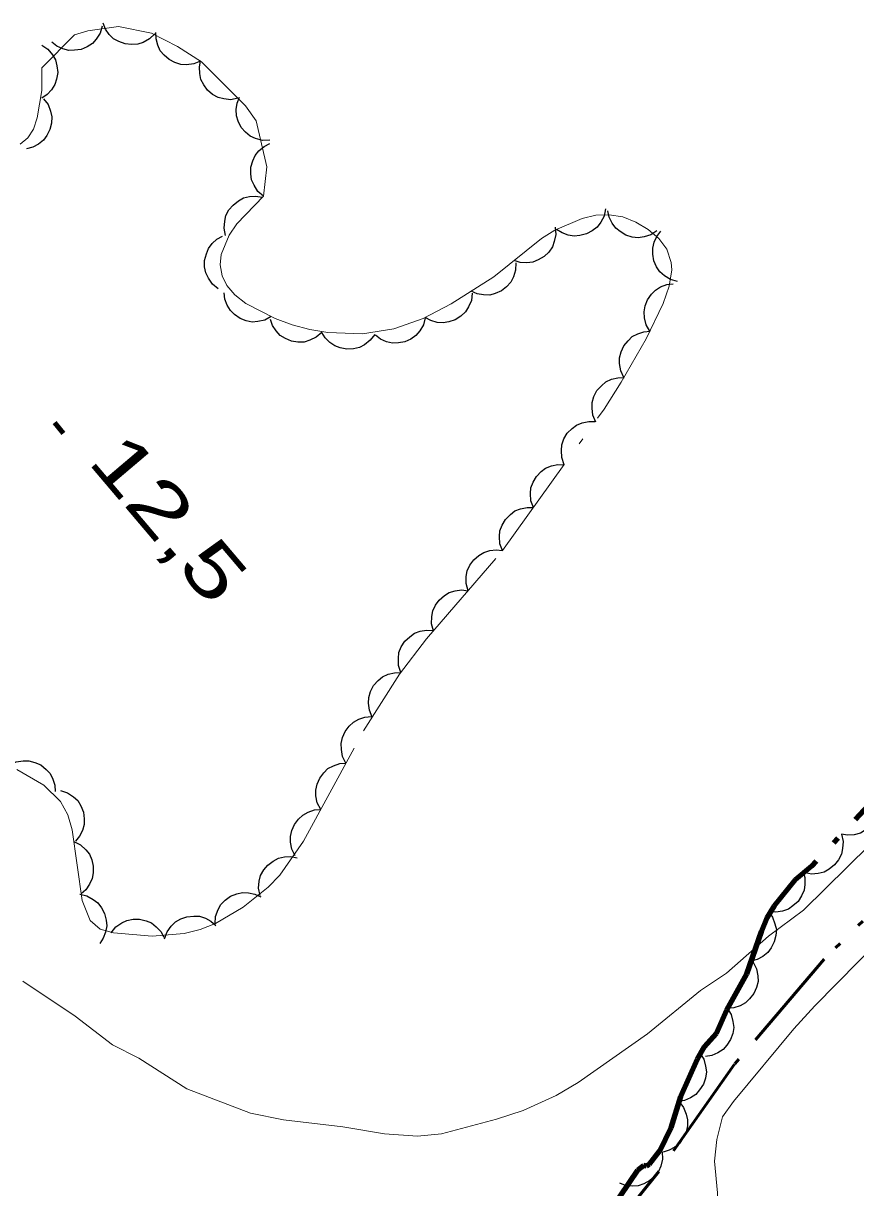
# Model space of a CAD drawing. Extents: x 386081 to 389416, y 5130568 to 5134082.
# Drawn here: x 387292.6 to 387339.8, y 5132364.4 to 5132430.4 of the extents above; entities that cross this region are included whole.
import ezdxf

# ---------------------------------------------------------------- set-up
doc = ezdxf.new("R2010")
doc.units = 0
doc.header["$LTSCALE"] = 1.2
for name, pattern in [('DASH_DOUBLE_DOT', [9.2, 5, -1.2, 0.3, -1.2, 0.3, -1.2]), ('DOT_DASHED', [7.7, 5, -1.2, 0.3, -1.2]), ('LONG_DASHED', [7.5, 6, -1.5])]:
    doc.linetypes.add(name, pattern=pattern)
for name, color, linetype, lineweight in [('2', 7, 'Continuous', 13), ('3', 7, 'Continuous', 140), ('4', 7, 'DASH_DOUBLE_DOT', 53), ('44', 7, 'Continuous', 25)]:
    doc.layers.add(name, color=color, linetype=linetype, lineweight=lineweight)

msp = doc.modelspace()

# ---------------------------------------------------------------- linework, layer by layer
at = {"layer": '2'}
for points in [[(387328.02, 5132373.16), (387331.01, 5132375.62), (387332.5, 5132376.6), (387334.87, 5132378.7), (387336.85, 5132380.17), (387340.59, 5132383.86)], [(387341.24, 5132378.55), (387337.5, 5132374.74), (387336.31, 5132373.45), (387332.88, 5132369.32), (387332.26, 5132368.46), (387331.94, 5132367.17), (387331.81, 5132365.94), (387331.98, 5132364.15), (387331.91, 5132362.48), (387332.15, 5132361.12), (387332.45, 5132360.07), (387332.81, 5132359.21), (387333.55, 5132358.34), (387334.17, 5132358.09), (387336.02, 5132357.84), (387337.2, 5132357.9), (387339.24, 5132358.32), (387341.03, 5132358.5)]]:
    msp.add_lwpolyline(points, dxfattribs=at)
at = {"layer": '2', "linetype": 'LONG_DASHED'}
msp.add_lwpolyline([(387292.61, 5132376.15), (387295.58, 5132374.16), (387297.69, 5132372.54), (387299.18, 5132371.79), (387301.91, 5132370.04), (387305.51, 5132368.66), (387307.38, 5132368.28), (387310.74, 5132367.89), (387313.1, 5132367.5), (387314.97, 5132367.37), (387316.34, 5132367.49), (387319.46, 5132368.33), (387320.96, 5132368.82), (387322.83, 5132369.67), (387324.08, 5132370.41), (387328.02, 5132373.16)], dxfattribs=at)
at = {"layer": '3'}
msp.add_line((387294.39, 5132407.81), (387294.9, 5132407.2), dxfattribs=at)
at = {"layer": '4'}
msp.add_lwpolyline([(387385.14, 5132422.65), (387378, 5132415.91), (387345.53, 5132384.75), (387338.02, 5132377.4), (387332.95, 5132371.44), (387328.66, 5132365.36), (387323.45, 5132358.88), (387320.1, 5132355.51), (387317.98, 5132352.68), (387317.57, 5132352.26), (387316.14, 5132350.32), (387313.69, 5132346.48), (387308.47, 5132338.84), (387304.07, 5132332.7)], dxfattribs=at)
at = {"layer": '44', "linetype": 'DOT_DASHED', "lineweight": 13}
for points in [[(387306.24, 5132420.64), (387306.44, 5132422.31), (387305.83, 5132424.91), (387305.22, 5132425.77), (387302.74, 5132428.26), (387301.38, 5132429.13), (387299.89, 5132429.88), (387298.02, 5132430.26), (387296.28, 5132430.02), (387295.53, 5132429.78), (387293.68, 5132427.92), (387293.68, 5132426.63), (387293.42, 5132425.09), (387293.2, 5132424.44), (387292.88, 5132423.94), (387292.45, 5132423.59)], [(387325.85, 5132419.59), (387325.09, 5132419.57), (387324.31, 5132419.37), (387322.76, 5132418.72), (387322, 5132418.25), (387319.31, 5132416.07), (387316.89, 5132414.53), (387315.29, 5132413.7), (387313.63, 5132413.12), (387311.85, 5132412.83), (387309.89, 5132412.91), (387308.88, 5132413.09), (387307.88, 5132413.34), (387306.91, 5132413.71), (387305.24, 5132414.55), (387304.62, 5132415.04), (387304.17, 5132415.57), (387303.9, 5132416.13), (387303.79, 5132416.75), (387303.84, 5132417.34), (387304.3, 5132418.44), (387304.73, 5132419.07), (387306.24, 5132420.64)], [(387292.26, 5132388.15), (387293.8, 5132387.26), (387294.74, 5132386.34), (387295.15, 5132385.57), (387295.4, 5132384.72), (387295.97, 5132380.71), (387296.43, 5132379.58), (387296.98, 5132379.09), (387297.74, 5132378.88), (387299.94, 5132378.7), (387301.75, 5132378.84), (387302.65, 5132379.07), (387303.52, 5132379.41), (387305.09, 5132380.34), (387306.52, 5132381.48), (387307.18, 5132382.15), (387308.51, 5132384.09), (387311.92, 5132390.34), (387313.96, 5132393.54), (387315.49, 5132395.55), (387319.8, 5132400.55), (387325.55, 5132408.57), (387326.52, 5132410.09), (387327.93, 5132412.55), (387328.91, 5132414.55), (387329.25, 5132415.54), (387329.39, 5132416.46), (387329.36, 5132416.88), (387329.11, 5132417.63), (387328.66, 5132418.25), (387328.05, 5132418.76), (387327.35, 5132419.17), (387326.61, 5132419.47), (387325.85, 5132419.59)]]:
    msp.add_lwpolyline(points, dxfattribs=at)
at = {"layer": '44'}
for points in [[(387297.11, 5132430.28), (387296.99, 5132429.88), (387296.77, 5132429.54), (387296.55, 5132429.29), (387296.25, 5132429.1), (387295.91, 5132428.96), (387295.53, 5132428.91), (387295.21, 5132428.9), (387294.87, 5132428.99), (387294.53, 5132429.15), (387294.25, 5132429.37)], [(387300.09, 5132429.84), (387299.79, 5132429.55), (387299.43, 5132429.36), (387299.12, 5132429.25), (387298.77, 5132429.23), (387298.4, 5132429.27), (387298.04, 5132429.41), (387297.75, 5132429.55), (387297.5, 5132429.8), (387297.29, 5132430.1), (387297.15, 5132430.44)], [(387302.67, 5132428.3), (387302.29, 5132428.14), (387301.89, 5132428.09), (387301.56, 5132428.1), (387301.22, 5132428.21), (387300.89, 5132428.38), (387300.61, 5132428.64), (387300.39, 5132428.88), (387300.25, 5132429.2), (387300.16, 5132429.56), (387300.15, 5132429.92)], [(387293.68, 5132429.2), (387294.03, 5132428.97), (387294.28, 5132428.65), (387294.45, 5132428.37), (387294.54, 5132428.03), (387294.58, 5132427.66), (387294.51, 5132427.28), (387294.42, 5132426.97), (387294.23, 5132426.67), (387293.98, 5132426.4), (387293.68, 5132426.2)], [(387304.8, 5132426.19), (387304.39, 5132426.11), (387303.99, 5132426.16), (387303.67, 5132426.23), (387303.36, 5132426.41), (387303.08, 5132426.65), (387302.86, 5132426.96), (387302.7, 5132427.25), (387302.63, 5132427.59), (387302.62, 5132427.96), (387302.68, 5132428.32)], [(387293.78, 5132426.16), (387294.04, 5132425.83), (387294.18, 5132425.45), (387294.25, 5132425.13), (387294.23, 5132424.77), (387294.14, 5132424.42), (387293.96, 5132424.08), (387293.77, 5132423.81), (387293.49, 5132423.59), (387293.17, 5132423.42), (387292.82, 5132423.32)], [(387306.61, 5132423.81), (387306.19, 5132423.8), (387305.8, 5132423.91), (387305.5, 5132424.04), (387305.23, 5132424.26), (387304.99, 5132424.54), (387304.82, 5132424.89), (387304.71, 5132425.2), (387304.7, 5132425.55), (387304.75, 5132425.92), (387304.88, 5132426.25)], [(387306.24, 5132420.64), (387305.92, 5132420.91), (387305.71, 5132421.26), (387305.57, 5132421.56), (387305.52, 5132421.91), (387305.53, 5132422.28), (387305.64, 5132422.64), (387305.77, 5132422.94), (387305.99, 5132423.21), (387306.28, 5132423.45), (387306.6, 5132423.62)], [(387304.1, 5132418.41), (387304.01, 5132418.82), (387304.05, 5132419.23), (387304.12, 5132419.55), (387304.29, 5132419.86), (387304.52, 5132420.14), (387304.83, 5132420.37), (387305.11, 5132420.54), (387305.45, 5132420.62), (387305.82, 5132420.64), (387306.18, 5132420.58)], [(387325.63, 5132419.92), (387325.55, 5132419.51), (387325.36, 5132419.16), (387325.16, 5132418.89), (387324.88, 5132418.67), (387324.56, 5132418.5), (387324.18, 5132418.41), (387323.86, 5132418.37), (387323.51, 5132418.44), (387323.17, 5132418.57), (387322.86, 5132418.76)], [(387328.55, 5132418.68), (387328.21, 5132418.45), (387327.82, 5132418.33), (387327.49, 5132418.28), (387327.14, 5132418.32), (387326.79, 5132418.43), (387326.46, 5132418.63), (387326.21, 5132418.83), (387326.01, 5132419.12), (387325.85, 5132419.46), (387325.77, 5132419.81)], [(387322.78, 5132418.88), (387322.82, 5132418.47), (387322.73, 5132418.07), (387322.62, 5132417.76), (387322.42, 5132417.47), (387322.15, 5132417.22), (387321.82, 5132417.03), (387321.52, 5132416.9), (387321.17, 5132416.87), (387320.8, 5132416.89), (387320.45, 5132416.99)], [(387303.67, 5132415.39), (387303.35, 5132415.65), (387303.12, 5132415.99), (387302.97, 5132416.29), (387302.91, 5132416.63), (387302.91, 5132417), (387303.01, 5132417.37), (387303.12, 5132417.68), (387303.34, 5132417.95), (387303.61, 5132418.2), (387303.93, 5132418.38)], [(387329.72, 5132415.8), (387329.32, 5132415.92), (387328.97, 5132416.13), (387328.72, 5132416.35), (387328.53, 5132416.64), (387328.38, 5132416.98), (387328.32, 5132417.36), (387328.31, 5132417.69), (387328.4, 5132418.03), (387328.55, 5132418.36), (387328.77, 5132418.65)], [(387320.55, 5132416.86), (387320.54, 5132416.44), (387320.41, 5132416.06), (387320.26, 5132415.76), (387320.02, 5132415.5), (387319.73, 5132415.28), (387319.38, 5132415.13), (387319.07, 5132415.03), (387318.71, 5132415.04), (387318.35, 5132415.1), (387318.02, 5132415.25)], [(387328.15, 5132412.99), (387327.94, 5132413.35), (387327.85, 5132413.75), (387327.82, 5132414.08), (387327.89, 5132414.42), (387328.02, 5132414.77), (387328.24, 5132415.08), (387328.46, 5132415.32), (387328.76, 5132415.5), (387329.11, 5132415.63), (387329.47, 5132415.68)], [(387306.69, 5132413.82), (387306.33, 5132413.61), (387305.93, 5132413.53), (387305.6, 5132413.5), (387305.26, 5132413.57), (387304.92, 5132413.71), (387304.61, 5132413.94), (387304.37, 5132414.16), (387304.19, 5132414.46), (387304.06, 5132414.81), (387304.01, 5132415.17)], [(387318.08, 5132415.15), (387318.03, 5132414.73), (387317.87, 5132414.36), (387317.69, 5132414.08), (387317.43, 5132413.84), (387317.12, 5132413.64), (387316.76, 5132413.52), (387316.44, 5132413.46), (387316.09, 5132413.49), (387315.73, 5132413.59), (387315.41, 5132413.76)], [(387309.55, 5132412.92), (387309.24, 5132412.64), (387308.87, 5132412.47), (387308.55, 5132412.37), (387308.2, 5132412.37), (387307.84, 5132412.43), (387307.49, 5132412.58), (387307.2, 5132412.74), (387306.96, 5132413), (387306.76, 5132413.31), (387306.64, 5132413.65)], [(387315.42, 5132413.75), (387315.31, 5132413.34), (387315.1, 5132413), (387314.89, 5132412.74), (387314.6, 5132412.54), (387314.26, 5132412.39), (387313.89, 5132412.33), (387313.56, 5132412.31), (387313.22, 5132412.39), (387312.88, 5132412.54), (387312.59, 5132412.76)], [(387312.55, 5132412.8), (387312.3, 5132412.47), (387311.98, 5132412.22), (387311.69, 5132412.06), (387311.34, 5132411.99), (387310.98, 5132411.97), (387310.6, 5132412.05), (387310.29, 5132412.15), (387310, 5132412.35), (387309.74, 5132412.62), (387309.55, 5132412.92)], [(387326.68, 5132410.37), (387326.5, 5132410.75), (387326.43, 5132411.15), (387326.42, 5132411.48), (387326.52, 5132411.82), (387326.67, 5132412.15), (387326.91, 5132412.45), (387327.15, 5132412.68), (387327.46, 5132412.84), (387327.81, 5132412.95), (387328.17, 5132412.98)], [(387325.08, 5132407.84), (387324.92, 5132408.22), (387324.87, 5132408.62), (387324.88, 5132408.95), (387324.98, 5132409.29), (387325.15, 5132409.62), (387325.41, 5132409.9), (387325.65, 5132410.12), (387325.98, 5132410.26), (387326.34, 5132410.35), (387326.7, 5132410.36)], [(387323.29, 5132405.42), (387323.15, 5132405.82), (387323.13, 5132406.22), (387323.15, 5132406.55), (387323.28, 5132406.88), (387323.46, 5132407.2), (387323.74, 5132407.47), (387323.99, 5132407.67), (387324.32, 5132407.8), (387324.68, 5132407.87), (387325.04, 5132407.86)], [(387321.55, 5132402.99), (387321.4, 5132403.38), (387321.38, 5132403.78), (387321.4, 5132404.11), (387321.53, 5132404.44), (387321.72, 5132404.76), (387321.99, 5132405.03), (387322.24, 5132405.23), (387322.57, 5132405.36), (387322.93, 5132405.43), (387323.29, 5132405.42)], [(387319.8, 5132400.55), (387319.65, 5132400.94), (387319.63, 5132401.35), (387319.65, 5132401.67), (387319.78, 5132402), (387319.97, 5132402.32), (387320.24, 5132402.59), (387320.49, 5132402.8), (387320.82, 5132402.92), (387321.19, 5132403), (387321.55, 5132402.99)], [(387317.84, 5132398.28), (387317.73, 5132398.68), (387317.74, 5132399.09), (387317.8, 5132399.41), (387317.95, 5132399.73), (387318.17, 5132400.03), (387318.46, 5132400.27), (387318.73, 5132400.45), (387319.07, 5132400.55), (387319.44, 5132400.59), (387319.8, 5132400.55)], [(387315.88, 5132396), (387315.77, 5132396.41), (387315.78, 5132396.81), (387315.84, 5132397.14), (387315.99, 5132397.46), (387316.21, 5132397.75), (387316.5, 5132398), (387316.77, 5132398.18), (387317.11, 5132398.28), (387317.48, 5132398.32), (387317.84, 5132398.28)], [(387314.04, 5132393.64), (387313.9, 5132394.03), (387313.89, 5132394.44), (387313.92, 5132394.77), (387314.06, 5132395.09), (387314.26, 5132395.41), (387314.54, 5132395.67), (387314.8, 5132395.87), (387315.13, 5132395.98), (387315.49, 5132396.05), (387315.85, 5132396.03)], [(387312.41, 5132391.12), (387312.25, 5132391.5), (387312.2, 5132391.9), (387312.21, 5132392.23), (387312.32, 5132392.57), (387312.49, 5132392.9), (387312.74, 5132393.18), (387312.99, 5132393.4), (387313.31, 5132393.54), (387313.67, 5132393.63), (387314.03, 5132393.64)], [(387310.92, 5132388.51), (387310.73, 5132388.88), (387310.66, 5132389.28), (387310.64, 5132389.61), (387310.73, 5132389.96), (387310.87, 5132390.29), (387311.11, 5132390.6), (387311.34, 5132390.83), (387311.65, 5132390.99), (387312, 5132391.11), (387312.36, 5132391.15)], [(387291.84, 5132388.39), (387292.22, 5132388.57), (387292.62, 5132388.64), (387292.95, 5132388.64), (387293.29, 5132388.55), (387293.63, 5132388.4), (387293.92, 5132388.15), (387294.15, 5132387.92), (387294.31, 5132387.6), (387294.42, 5132387.25), (387294.44, 5132386.89)], [(387309.49, 5132385.88), (387309.29, 5132386.25), (387309.22, 5132386.65), (387309.21, 5132386.98), (387309.29, 5132387.32), (387309.44, 5132387.66), (387309.67, 5132387.96), (387309.9, 5132388.2), (387310.21, 5132388.36), (387310.57, 5132388.48), (387310.92, 5132388.51)], [(387294.74, 5132386.96), (387295.14, 5132386.83), (387295.47, 5132386.6), (387295.72, 5132386.38), (387295.9, 5132386.08), (387296.04, 5132385.73), (387296.08, 5132385.35), (387296.09, 5132385.03), (387295.98, 5132384.69), (387295.82, 5132384.36), (387295.59, 5132384.08)], [(387341.05, 5132386.67), (387341.14, 5132386.27), (387341.12, 5132385.86), (387341.05, 5132385.54), (387340.88, 5132385.23), (387340.66, 5132384.94), (387340.35, 5132384.7), (387340.08, 5132384.53), (387339.73, 5132384.45), (387339.36, 5132384.42), (387339.01, 5132384.48)], [(387308.05, 5132383.25), (387307.86, 5132383.62), (387307.78, 5132384.02), (387307.77, 5132384.35), (387307.85, 5132384.69), (387308, 5132385.03), (387308.24, 5132385.33), (387308.47, 5132385.56), (387308.78, 5132385.73), (387309.13, 5132385.85), (387309.49, 5132385.88)], [(387339.01, 5132384.48), (387339.1, 5132384.07), (387339.07, 5132383.66), (387339.01, 5132383.34), (387338.84, 5132383.03), (387338.62, 5132382.74), (387338.31, 5132382.5), (387338.03, 5132382.33), (387337.69, 5132382.25), (387337.32, 5132382.22), (387336.97, 5132382.28)], [(387295.49, 5132384.06), (387295.87, 5132383.88), (387296.17, 5132383.6), (387296.38, 5132383.35), (387296.51, 5132383.02), (387296.6, 5132382.66), (387296.59, 5132382.28), (387296.54, 5132381.96), (387296.39, 5132381.64), (387296.18, 5132381.33), (387295.92, 5132381.09)], [(387306.05, 5132381), (387305.97, 5132381.41), (387306.01, 5132381.82), (387306.08, 5132382.14), (387306.26, 5132382.45), (387306.49, 5132382.73), (387306.8, 5132382.95), (387307.09, 5132383.12), (387307.43, 5132383.19), (387307.8, 5132383.21), (387308.16, 5132383.14)], [(387336.82, 5132382.43), (387336.94, 5132382.03), (387336.94, 5132381.62), (387336.9, 5132381.3), (387336.75, 5132380.98), (387336.55, 5132380.67), (387336.26, 5132380.41), (387336, 5132380.22), (387335.66, 5132380.12), (387335.29, 5132380.06), (387334.94, 5132380.09)], [(387303.51, 5132379.4), (387303.53, 5132379.82), (387303.67, 5132380.2), (387303.83, 5132380.49), (387304.08, 5132380.74), (387304.38, 5132380.96), (387304.73, 5132381.1), (387305.05, 5132381.18), (387305.4, 5132381.16), (387305.76, 5132381.08), (387306.09, 5132380.93)], [(387295.83, 5132381.07), (387296.23, 5132380.98), (387296.59, 5132380.78), (387296.86, 5132380.59), (387297.07, 5132380.31), (387297.24, 5132379.98), (387297.32, 5132379.6), (387297.36, 5132379.28), (387297.29, 5132378.93), (387297.16, 5132378.59), (387296.96, 5132378.29)], [(387300.63, 5132378.55), (387300.78, 5132378.95), (387301.02, 5132379.27), (387301.25, 5132379.51), (387301.56, 5132379.68), (387301.9, 5132379.8), (387302.29, 5132379.84), (387302.61, 5132379.83), (387302.95, 5132379.71), (387303.27, 5132379.54), (387303.54, 5132379.3)], [(387334.85, 5132380.12), (387335.1, 5132379.78), (387335.24, 5132379.4), (387335.32, 5132379.08), (387335.29, 5132378.73), (387335.2, 5132378.37), (387335.02, 5132378.03), (387334.83, 5132377.77), (387334.56, 5132377.55), (387334.23, 5132377.37), (387333.88, 5132377.28)], [(387297.61, 5132378.89), (387297.87, 5132379.22), (387298.21, 5132379.45), (387298.5, 5132379.59), (387298.85, 5132379.66), (387299.22, 5132379.66), (387299.59, 5132379.56), (387299.9, 5132379.45), (387300.17, 5132379.23), (387300.42, 5132378.96), (387300.6, 5132378.65)], [(387334.01, 5132377.22), (387334.2, 5132376.85), (387334.27, 5132376.45), (387334.28, 5132376.12), (387334.19, 5132375.78), (387334.04, 5132375.44), (387333.8, 5132375.14), (387333.57, 5132374.91), (387333.26, 5132374.75), (387332.9, 5132374.64), (387332.54, 5132374.61)], [(387332.53, 5132374.61), (387332.76, 5132374.26), (387332.86, 5132373.86), (387332.9, 5132373.53), (387332.85, 5132373.19), (387332.72, 5132372.84), (387332.51, 5132372.52), (387332.3, 5132372.27), (387332.01, 5132372.08), (387331.67, 5132371.93), (387331.31, 5132371.87)], [(387330.98, 5132372.07), (387331.2, 5132371.72), (387331.31, 5132371.33), (387331.35, 5132371), (387331.3, 5132370.65), (387331.18, 5132370.3), (387330.97, 5132369.98), (387330.76, 5132369.73), (387330.46, 5132369.54), (387330.12, 5132369.39), (387329.77, 5132369.33)], [(387329.8, 5132369.32), (387330.06, 5132368.99), (387330.21, 5132368.61), (387330.29, 5132368.29), (387330.28, 5132367.94), (387330.2, 5132367.58), (387330.02, 5132367.24), (387329.85, 5132366.97), (387329.57, 5132366.74), (387329.25, 5132366.56), (387328.91, 5132366.45)], [(387328.85, 5132366.47), (387328.87, 5132366.05), (387328.77, 5132365.66), (387328.64, 5132365.35), (387328.42, 5132365.08), (387328.14, 5132364.84), (387327.8, 5132364.66), (387327.49, 5132364.55), (387327.14, 5132364.53), (387326.77, 5132364.57), (387326.44, 5132364.69)]]:
    msp.add_lwpolyline(points, dxfattribs=at)
at = {"layer": '44', "linetype": 'DOT_DASHED', "lineweight": 90}
msp.add_lwpolyline([(387343.87, 5132389.71), (387337.32, 5132382.66), (387336.39, 5132381.9), (387335.19, 5132380.41), (387334.77, 5132379.73), (387334.45, 5132378.94), (387333.63, 5132376.54), (387332.49, 5132374.51), (387331.9, 5132373.19), (387331.22, 5132372.42), (387330.83, 5132371.73), (387329.89, 5132369.61), (387329.34, 5132367.84), (387328.69, 5132366.51), (387328.1, 5132365.76), (387327.95, 5132365.67), (387327.79, 5132365.69), (387327.45, 5132365.44), (387325.96, 5132363.22)], dxfattribs=at)

# ---------------------------------------------------------------- texts
at = {"layer": '3', "width": 1.4}
msp.add_text('12,5   ', height=3, rotation=310.294, dxfattribs=at).set_placement((387296.22, 5132405.59))

doc.saveas('drawing.dxf')
